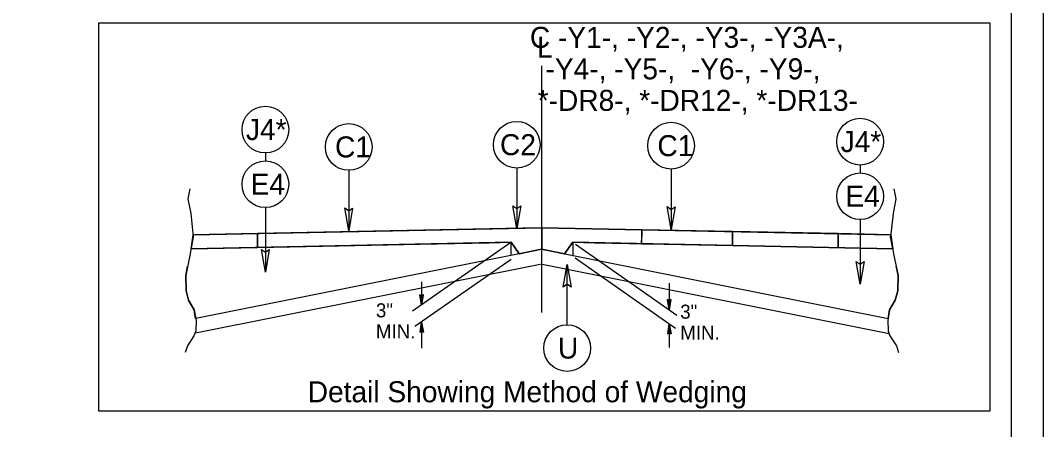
# Model space of a CAD drawing. Extents: x 18938 to 19565, y 6931 to 7973.
# Drawn here: x 19309.4 to 19382.4, y 7871.6 to 7900.8 of the extents above; entities that cross this region are included whole.
import ezdxf

# ---------------------------------------------------------------- set-up
doc = ezdxf.new("R2010")
doc.units = 0
for name, color, linetype in [('Old_Level_11', 7, 'Continuous'), ('Old_Level_2', 7, 'Continuous'), ('Prop Dimension', 7, 'Continuous'), ('Prop Terminator CELL', 7, 'Continuous'), ('Typical Hinge Slope Arterial CELL', 7, 'Continuous'), ('Typical ID Circle CELL', 7, 'Continuous'), ('Typical Pavement Slope Information CELL', 7, 'Continuous'), ('Typical Terminator CELL', 7, 'Continuous'), ('Typical Text General CELL', 7, 'Continuous'), ('Typical Text ID Circle CELL', 7, 'Continuous'), ('Typical Text Label CELL', 7, 'Continuous')]:
    doc.layers.add(name, color=color, linetype=linetype)

# ---------------------------------------------------------------- blocks, each defined once
blk = doc.blocks.new('TERMINATOR')
at = {"layer": 'Typical Text General CELL'}
blk.add_lwpolyline([(-0.469, 0.081), (0, 0), (-0.471, -0.083), (-0.411, 0)], close=True, dxfattribs=at)

msp = doc.modelspace()

# ---------------------------------------------------------------- linework, layer by layer
at = {"layer": 'Old_Level_2'}
msp.add_lwpolyline([(19315.008, 7872.884), (19378.62, 7872.884), (19378.62, 7900.579), (19315.008, 7900.579)], close=True, dxfattribs=at)
at = {"layer": 'Prop Dimension'}
msp.add_lwpolyline([(19155.167, 7813.281), (19382.434, 7813.281), (19382.434, 7959.715), (19155.167, 7959.715)], close=True, dxfattribs=at)
at = {"layer": 'Typical Hinge Slope Arterial CELL'}
for p, q in [((19326.341, 7885.565), (19321.748, 7885.473)), ((19345.284, 7885.943), (19326.341, 7885.565)), ((19326.341, 7885.565), (19326.341, 7884.567)), ((19326.341, 7884.567), (19326.341, 7885.565)), ((19345.288, 7885.919), (19345.284, 7885.943)), ((19345.293, 7885.943), (19345.288, 7885.919)), ((19346.639, 7885.97), (19345.293, 7885.943)), ((19346.64, 7885.97), (19346.639, 7885.97)), ((19346.64, 7884.433), (19346.64, 7885.97)), ((19353.763, 7885.828), (19353.75, 7884.817)), ((19353.763, 7885.338), (19353.763, 7885.828)), ((19360.23, 7885.699), (19353.763, 7885.828)), ((19360.23, 7885.699), (19360.228, 7884.693)), ((19360.23, 7885.338), (19360.23, 7885.699)), ((19367.789, 7885.548), (19360.23, 7885.699)), ((19367.789, 7884.551), (19367.789, 7885.548)), ((19371.531, 7885.473), (19367.789, 7885.548)), ((19367.789, 7885.548), (19367.789, 7884.551)), ((19321.748, 7885.473), (19321.745, 7885.45)), ((19339.169, 7884.824), (19339.169, 7884.824)), ((19344.456, 7884.929), (19345.015, 7884.11)), ((19348.264, 7884.11), (19348.828, 7884.91)), ((19348.828, 7884.91), (19348.842, 7884.929)), ((19348.842, 7884.929), (19350.398, 7884.898)), ((19353.685, 7884.833), (19353.75, 7884.817)), ((19353.75, 7884.817), (19353.763, 7885.338)), ((19353.75, 7884.817), (19353.838, 7884.83)), ((19353.75, 7884.817), (19353.75, 7884.817)), ((19353.838, 7884.83), (19354.11, 7884.824)), ((19354.11, 7884.824), (19354.11, 7884.824)), ((19360.228, 7884.702), (19360.23, 7885.338)), ((19360.23, 7885.338), (19360.23, 7885.338)), ((19371.534, 7885.453), (19371.531, 7885.473)), ((19321.607, 7884.473), (19326.341, 7884.567)), ((19321.61, 7884.499), (19321.607, 7884.473)), ((19345.015, 7884.11), (19346.602, 7884.44)), ((19346.602, 7884.44), (19346.64, 7884.432)), ((19346.64, 7884.432), (19346.64, 7884.433)), ((19346.64, 7884.432), (19346.64, 7884.432)), ((19346.64, 7884.432), (19348.264, 7884.11)), ((19360.228, 7884.693), (19360.283, 7884.701)), ((19360.228, 7884.693), (19360.228, 7884.693)), ((19360.283, 7884.701), (19367.789, 7884.551)), ((19367.789, 7884.551), (19371.673, 7884.473))]:
    msp.add_line(p, q, dxfattribs=at)
for points in [[(19353.763, 7885.828), (19346.642, 7885.97), (19346.64, 7885.97)], [(19346.64, 7885.97), (19346.64, 7884.433), (19346.64, 7884.432)], [(19321.745, 7885.45), (19321.759, 7885.314), (19321.61, 7884.499)], [(19326.341, 7884.567), (19337.928, 7884.799), (19339.169, 7884.824)], [(19339.169, 7884.824), (19340.399, 7884.848), (19342.881, 7884.898), (19344.456, 7884.929)], [(19339.169, 7884.824), (19339.169, 7884.824)], [(19350.398, 7884.898), (19352.88, 7884.849), (19353.685, 7884.833)], [(19354.11, 7884.824), (19354.11, 7884.824)], [(19354.11, 7884.824), (19355.353, 7884.799), (19360.228, 7884.702)], [(19371.673, 7884.473), (19371.52, 7885.314), (19371.534, 7885.453)]]:
    msp.add_lwpolyline(points, dxfattribs=at)
at = {"layer": 'Typical ID Circle CELL'}
for p, q in [((19346.639, 7885.97), (19321.748, 7885.473)), ((19321.748, 7885.473), (19346.639, 7885.97)), ((19346.639, 7885.97), (19371.531, 7885.473)), ((19346.642, 7885.97), (19371.531, 7885.473)), ((19321.607, 7884.473), (19321.748, 7885.473)), ((19344.456, 7884.929), (19321.607, 7884.473)), ((19344.456, 7884.929), (19321.607, 7884.473)), ((19344.427, 7884.911), (19337.414, 7879.999)), ((19344.424, 7884.92), (19344.424, 7884.053)), ((19345.015, 7884.11), (19344.456, 7884.929)), ((19344.456, 7884.903), (19345.015, 7884.11)), ((19348.842, 7884.929), (19348.264, 7884.11)), ((19348.842, 7884.929), (19348.264, 7884.11)), ((19348.805, 7884.911), (19348.841, 7884.909)), ((19348.842, 7884.929), (19371.674, 7884.473)), ((19371.674, 7884.473), (19348.842, 7884.929)), ((19348.856, 7884.92), (19348.856, 7883.965)), ((19349.032, 7884.797), (19356.257, 7879.736)), ((19371.531, 7885.473), (19371.674, 7884.473)), ((19346.677, 7884.44), (19321.935, 7879.49)), ((19346.602, 7884.44), (19345.015, 7884.11)), ((19346.602, 7884.44), (19371.345, 7879.49)), ((19348.264, 7884.11), (19346.602, 7884.44)), ((19346.63, 7883.375), (19321.927, 7878.433)), ((19344.444, 7883.711), (19337.581, 7878.906)), ((19346.649, 7883.375), (19371.41, 7878.422)), ((19349.022, 7883.813), (19356.177, 7878.804)), ((19338.053, 7882.116), (19338.053, 7880.447)), ((19355.729, 7882.02), (19355.729, 7880.107)), ((19338.053, 7880.447), (19337.924, 7881.179)), ((19338.053, 7881.083), (19337.924, 7881.179)), ((19338.053, 7880.447), (19337.942, 7881.165)), ((19337.961, 7881.151), (19338.053, 7880.447)), ((19338.053, 7880.447), (19337.979, 7881.138)), ((19337.998, 7881.125), (19338.053, 7880.447)), ((19338.053, 7880.447), (19338.016, 7881.111)), ((19338.053, 7880.447), (19338.183, 7881.179)), ((19338.183, 7881.179), (19338.053, 7881.083)), ((19338.165, 7881.165), (19338.053, 7880.447)), ((19338.053, 7880.447), (19338.144, 7881.151)), ((19338.126, 7881.138), (19338.053, 7880.447)), ((19338.053, 7880.447), (19338.108, 7881.125)), ((19338.09, 7881.111), (19338.053, 7880.447)), ((19338.035, 7881.097), (19338.053, 7880.447)), ((19338.053, 7880.447), (19338.071, 7881.097)), ((19338.053, 7881.083), (19338.053, 7880.447)), ((19355.729, 7880.107), (19355.6, 7880.839)), ((19355.729, 7880.744), (19355.6, 7880.839)), ((19355.729, 7880.107), (19355.619, 7880.825)), ((19355.637, 7880.812), (19355.729, 7880.107)), ((19355.729, 7880.107), (19355.655, 7880.798)), ((19355.673, 7880.784), (19355.729, 7880.107)), ((19355.729, 7880.107), (19355.692, 7880.771)), ((19355.71, 7880.758), (19355.729, 7880.107)), ((19355.729, 7880.107), (19355.858, 7880.839)), ((19355.858, 7880.839), (19355.729, 7880.744)), ((19355.839, 7880.825), (19355.729, 7880.107)), ((19355.729, 7880.107), (19355.821, 7880.812)), ((19355.802, 7880.798), (19355.729, 7880.107)), ((19355.729, 7880.107), (19355.784, 7880.784)), ((19355.766, 7880.771), (19355.729, 7880.107)), ((19355.729, 7880.107), (19355.748, 7880.758)), ((19355.729, 7880.744), (19355.729, 7880.107)), ((19338.053, 7879.236), (19337.924, 7878.504)), ((19337.942, 7878.518), (19338.053, 7879.236)), ((19338.053, 7879.236), (19337.961, 7878.531)), ((19337.979, 7878.546), (19338.053, 7879.236)), ((19338.053, 7879.236), (19337.998, 7878.559)), ((19338.016, 7878.572), (19338.053, 7879.236)), ((19338.053, 7879.236), (19338.035, 7878.585)), ((19338.053, 7879.236), (19338.053, 7877.357)), ((19338.053, 7879.236), (19338.183, 7878.504)), ((19338.053, 7878.599), (19338.053, 7879.236)), ((19338.071, 7878.585), (19338.053, 7879.236)), ((19338.053, 7879.236), (19338.09, 7878.572)), ((19338.108, 7878.559), (19338.053, 7879.236)), ((19338.053, 7879.236), (19338.126, 7878.546)), ((19338.144, 7878.531), (19338.053, 7879.236)), ((19338.053, 7879.236), (19338.165, 7878.518)), ((19355.729, 7879.117), (19355.6, 7878.385)), ((19355.619, 7878.4), (19355.729, 7879.117)), ((19355.729, 7879.117), (19355.637, 7878.412)), ((19355.655, 7878.427), (19355.729, 7879.117)), ((19355.729, 7879.117), (19355.673, 7878.44)), ((19355.692, 7878.453), (19355.729, 7879.117)), ((19355.729, 7879.117), (19355.71, 7878.466)), ((19355.729, 7879.117), (19355.729, 7877.406)), ((19355.729, 7879.117), (19355.858, 7878.385)), ((19355.729, 7878.48), (19355.729, 7879.117)), ((19355.748, 7878.466), (19355.729, 7879.117)), ((19355.729, 7879.117), (19355.766, 7878.453)), ((19355.784, 7878.44), (19355.729, 7879.117)), ((19355.729, 7879.117), (19355.802, 7878.427)), ((19355.821, 7878.412), (19355.729, 7879.117)), ((19355.729, 7879.117), (19355.839, 7878.4)), ((19337.924, 7878.504), (19338.053, 7878.599)), ((19338.053, 7878.599), (19338.183, 7878.504)), ((19355.6, 7878.385), (19355.729, 7878.48)), ((19355.729, 7878.48), (19355.858, 7878.385))]:
    msp.add_line(p, q, dxfattribs=at)
for points in [[(19321.517, 7888.758), (19321.384, 7888.029), (19321.584, 7886.992), (19321.759, 7885.314), (19321.517, 7883.989), (19321.23, 7882.554), (19321.252, 7881.471), (19321.429, 7880.788), (19321.827, 7880.102), (19321.959, 7879.352), (19321.937, 7878.602), (19321.804, 7878.248), (19321.341, 7877.541), (19321.187, 7877.055)], [(19371.762, 7888.758), (19371.895, 7888.029), (19371.696, 7886.992), (19371.52, 7885.314), (19371.762, 7883.989), (19372.049, 7882.554), (19372.027, 7881.471), (19371.85, 7880.788), (19371.453, 7880.102), (19371.321, 7879.352), (19371.342, 7878.602), (19371.475, 7878.248), (19371.938, 7877.541), (19372.092, 7877.055)], [(19371.531, 7885.473), (19346.64, 7885.97), (19321.748, 7885.473)], [(19321.934, 7879.49), (19321.827, 7880.102), (19321.429, 7880.788), (19321.252, 7881.471), (19321.23, 7882.554), (19321.363, 7883.219)], [(19371.345, 7879.49), (19371.453, 7880.102), (19371.85, 7880.788), (19372.027, 7881.471), (19372.049, 7882.554), (19371.916, 7883.219)]]:
    msp.add_lwpolyline(points, dxfattribs=at)
at = {"layer": 'Typical Pavement Slope Information CELL'}
msp.add_lwpolyline([(19380.142, 7956.708), (19177.642, 7956.708), (19177.642, 7816.292), (19380.142, 7816.292)], close=True, dxfattribs=at)
at = {"layer": 'Typical Terminator CELL'}
for p, q in [((19326.909, 7891.306), (19326.909, 7890.74)), ((19332.857, 7890.068), (19332.857, 7885.758)), ((19344.846, 7890.229), (19344.846, 7885.919)), ((19355.858, 7890.16), (19355.858, 7885.85)), ((19369.345, 7890.448), (19369.345, 7889.882)), ((19326.909, 7887.405), (19326.909, 7882.797)), ((19369.345, 7886.546), (19369.345, 7881.939)), ((19348.441, 7879.04), (19348.441, 7883.35))]:
    msp.add_line(p, q, dxfattribs=at)
for centre in [(19326.909, 7892.974), (19344.846, 7891.896), (19369.345, 7892.116), (19332.858, 7891.736), (19355.858, 7891.828), (19326.909, 7889.072), (19369.345, 7888.214), (19348.441, 7877.373)]:
    msp.add_circle(centre, 1.668, dxfattribs=at)
at = {"layer": 'Typical Text ID Circle CELL'}
msp.add_line((19346.64, 7879.91), (19346.64, 7897.534), dxfattribs=at)

# ---------------------------------------------------------------- block references
at = {"layer": 'Typical Text General CELL', "xscale": 3.45, "yscale": 3.45}
for p, rotation in [((19332.857, 7885.758), -90.00000000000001), ((19344.846, 7885.919), -90.00000000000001), ((19355.858, 7885.85), -90.00000000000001), ((19326.909, 7882.797), -90.00000000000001), ((19348.441, 7883.35), 89.99999999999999), ((19369.345, 7881.939), -90.00000000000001)]:
    msp.add_blockref('TERMINATOR', p, dxfattribs=dict(at, rotation=rotation))

# ---------------------------------------------------------------- texts
at = {"layer": 'Old_Level_11'}
msp.add_text('Detail Showing Method of Wedging', height=1.5, rotation=360, dxfattribs=at).set_placement((19329.932, 7873.506))
at = {"layer": 'Prop Terminator CELL'}
for p in [(19325.521, 7892.227), (19367.957, 7891.369)]:
    msp.add_text('J4*', height=1.5, dxfattribs=at).set_placement(p)
for s, p in [('C1', (19331.88, 7890.99)), ('C2', (19343.651, 7891.15)), ('C1', (19354.881, 7891.081)), ('E4', (19325.855, 7888.326)), ('E4', (19368.292, 7887.468)), ('U', (19347.787, 7876.626))]:
    msp.add_text(s, height=1.5, rotation=360, dxfattribs=at).set_placement(p)
at = {"layer": 'Typical ID Circle CELL'}
for s, p in [('3"', (19334.796, 7879.57)), ('3"', (19356.508, 7879.475)), ('MIN.', (19334.796, 7878.07)), ('MIN.', (19356.508, 7877.975))]:
    msp.add_text(s, height=1, rotation=360, dxfattribs=at).set_placement(p)
at = {"layer": 'Typical Text Label CELL'}
for s, p in [('C -Y1-, -Y2-, -Y3-, -Y3A-,', (19345.783, 7898.815)), ('L', (19346.299, 7898.108)), ('  -Y4-, -Y5-,  -Y6-, -Y9-,', (19345.783, 7896.565)), (' *-DR8-, *-DR12-, *-DR13-', (19345.783, 7894.315))]:
    msp.add_text(s, height=1.5, dxfattribs=at).set_placement(p)

doc.saveas('drawing.dxf')
